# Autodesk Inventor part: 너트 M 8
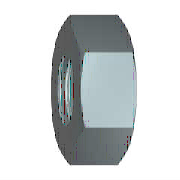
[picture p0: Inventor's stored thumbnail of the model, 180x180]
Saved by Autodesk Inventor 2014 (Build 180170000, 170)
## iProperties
IsCustomPart: 1
Created: 2012-02
Part Number: 너트 M 8
Material: 강철, 연강
Description: 6각 너트 및 6각 가는 너트
Document SubType Name: Modeling
Standard: KS B 1012
Designer: mduedu
Standards Organization: KS
Language: ko-KR
Size Designation: M 8
Categories: <MemberInstance><Categories><Category DisplayName="조임쇠" InternalName="e4da775c-781d-43d5-af7c-5136215cf5a6" Mnemonic="FSTN"><Category DisplayName="너트" InternalN
Density: 7.86 g/cm^3
Mass: 4.30432 g
Surface Area: 5.27675 cm^2
Volume: 0.547623 cm^3
Appearance: 강철
Author: mduedu
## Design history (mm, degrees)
sketch "스케치1"
  geometry: L1 (-7.506, 0)-(-3.753, 6.5); L2 (-3.753, 6.5)-(3.753, 6.5); L3 (3.753, 6.5)-(7.506, 0); L4 (7.506, 0)-(3.753, -6.5); L5 (3.753, -6.5)-(-3.753, -6.5); L6 (-3.753, -6.5)-(-7.506, 0); 2 further points
  constraints: 12 end point, 1 coincident, 1 horizontal, 11 other
  dimensions: "d0" = 15.01111 distance of L3.end L1.start (= 1.1547 x SW)
extrude "본체" new body sketch "스케치1" distance "d1" = 5 (= KOH); taper "d2" = 0 deg
sketch "스케치2"
  geometry: L1 (0, 3.753)-(0, 7.506) reference; L2 (0, 7.506)-(5, 7.506) reference; L3 (5, 3.753)-(5, 7.506) reference; L4 (-1, 0)-(6, 0) reference; L5 (0.581, 7.506)-(0, 6.5); L6 (4.419, 7.506)-(5, 6.5)
  constraints: 4 end point, 4 point on line
  dimensions: "d3" = 30 deg angle of L1 L5 (= ANG1); "d4" = 30 deg angle of L3 L6 (= ANG2); "d5" = 13 diameter of L5.end L4 (= SW0); "d6" = 13 diameter of L6.end L4 (= SW01)
revolve "모따기1" sketch "스케치2" stored, may be unused: angle "d7" = 90 deg
sketch "스케치3"
  geometry: A1 r 6.5 centre (0, 0) between (-3.25, -5.629) and (3.25, -5.629) reference; 1 further point
  constraints: 1 coincident
hole "스레드" sketch "스케치3" at (0, 0) diameter "d25" = 6.647; stored, may be unused: countersink angle "d29" = 82 deg, drill point angle "d31" = 118 deg; dims "d26" = 6, "d27" = 4, "d28" = 2, "d30" = 8
workaxis "Work Axis1"
workplane "Work Plane1"
body "Solid1"
chamfer "모따기2" distance "d8" = 0.67658 (= -0.5 x GD1 + 0.5 x NND); stored, may be unused: angle "d9" = 30 deg, second distance "d40" = 0.67658 (= -0.5 x GD1 + 0.5 x NND)
chamfer "모따기3" distance "d10" = 0.67658 (= -0.5 x GD1 + 0.5 x NND); stored, may be unused: angle "d11" = 30 deg, second distance "d41" = 0.67658 (= -0.5 x GD1 + 0.5 x NND)
other parameters: "ANG1" = 30 deg [user parameter; used in 1 equation term], "ANG2" = 30 deg [user parameter; used in 1 equation term], "NND" = 8 [user parameter; used in 4 equation terms], "KOH" = 5 [user parameter; used in 1 equation term], "SW" = 13 [user parameter; used in 4 equation terms], "SW0" = 13 (= SW) [user parameter; used in 1 equation term], "SW01" = 13 (= SW) [user parameter; used in 1 equation term], "GD1" = 6.64684 (computed from THREADDIA, PTC, TOA) [user parameter; used in 4 equation terms], "d13" = 0, "d14" = 0, "d39" = 0, "d42" = 0, "GUL" = 0.67658 (= 0.541266 x PTC) [user parameter], "TPU" = 8 (computed from PTC) [user parameter], "THREADDIA" = 8 [user parameter; used in 1 equation term], "TOA" = 30 deg [user parameter; used in 1 equation term], "PTC" = 1.25 [user parameter; used in 4 equation terms], "E0" = 15.015 (= 1.155 x SW) [user parameter], "GAL" = 0.67658 (= 0.541266 x PTC) [user parameter]
